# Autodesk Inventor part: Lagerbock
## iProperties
Shininess: 64.0
Length Units: 11269
Angle Units: 11279
Time Units: 11290
Mass Units: 11283
Length Display Precision: 3
Angle Display Precision: 2
Compacted: True
Part Number: Lagerbock
Document SubType Name: Modeling
Created: 2005-08
Material: Standard
Designer: Kumpf
Density: 0.0
Volumn: 0.0
Area: 0.0
PropertySet Name: Model Information
Control State: 0
Master: False
Checked Out: False
Author: Kumpf
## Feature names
1. Extrusion1
2. Bohrung1 [Hole]
3. Extrusion2
4. Rundung1 [Fillet]
5. Bohrung2 [Hole]
